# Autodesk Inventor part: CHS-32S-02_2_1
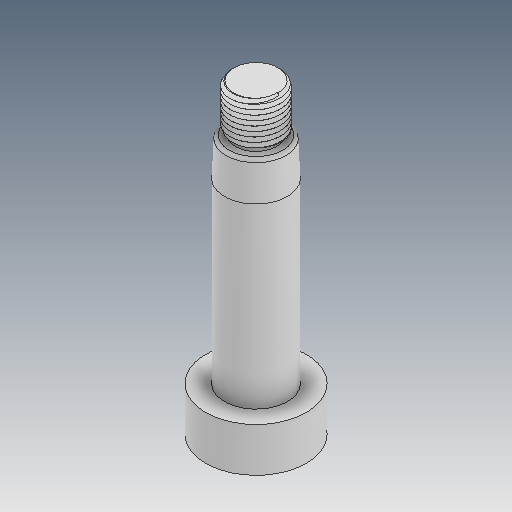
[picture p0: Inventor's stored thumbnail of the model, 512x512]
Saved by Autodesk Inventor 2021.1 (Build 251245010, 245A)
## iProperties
Created: 2021-05
Part Number: CHS-32S-02_2_1
Material: Ogólny
Document SubType Name: Modeling
Designer: user
Density: 1 g/cm^3
Appearance: Domyślna
Author: user
Revision Number: ÈÎºÎ
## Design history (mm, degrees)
feature "ÊäÈë1"
feature "ÊäÈë2"
node "Bryła1"
node "Bryła2"
